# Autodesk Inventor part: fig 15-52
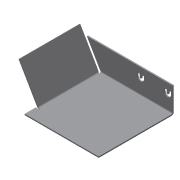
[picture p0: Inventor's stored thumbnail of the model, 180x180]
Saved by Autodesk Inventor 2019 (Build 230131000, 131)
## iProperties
Shininess: 77.0
Angle Display Precision: 2
Document Length Units: 11269
Document Angle Units: 11279
Document Time Units: 11290
Document Mass Units: 11283
Document Length Units Precision: 3
Document Angle Units Precision: 2
Created: 2002-04
Part Number: fig 15-52
Document SubType Name: Sheet Metal
Density: 1 g/cm^3
Sheet Metal Rule: Default
Material: Generic
Appearance: Default
Density: 0.0
Volumn: 0.0
Area: 0.0
PropertySet Name: Model Information
Control State: 0
Master: False
Checked Out: False
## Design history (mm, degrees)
node "Face1"
  sketch "Sketch1"
    geometry: L1 (12.647, 25.882)-(12.647, -14.118); L2 (12.647, -14.118)-(-17.353, -14.118); L3 (-17.353, -14.118)-(-17.353, 15.882); L4 (-17.353, 15.882)-(-2.353, 15.882); L5 (-2.353, 15.882)-(-2.353, 25.882); L6 (-2.353, 25.882)-(12.647, 25.882); 1 further point
    constraints: 12 end point, 4 parallel, 1 perpendicular
    dimensions: "d5" = 30 distance of L2.end L3.end; "d6" = 10 distance of L4.end L5.end; "d7" = 15 distance of L3.end L4.end; "d25" = 15 distance of L5.end L1.start
sketch "Sketch3"
  geometry: L1 (10, -15)-(10, 0)
  constraints: 2 end point
feature "Fold3" sketch "Sketch3" dims "d26" = 0.5 (= BendRadius), "d27" = 90 deg, "d28" = 0.5 (= BendRadius), "d96" = 0.5 (= BendReliefWidth), "d97" = 0.25 (= BendReliefDepth), "d98" = 1 (= MinimumRemnant), "d112" = 0.5 (= Thickness), "SeamGap" = 0.01
node "Flange2"
sketch "Sketch6"
  geometry: L1 (-6.914, 3.413)-(-5.843, 3.413); L2 (-5.843, 0.624)-(-6.914, 0.624); L3 (-6.914, 2.432)-(-5.843, 2.432); L4 (-5.843, 1.605)-(-6.914, 1.605); L5 (-6.914, 0.624)-(-6.914, 1.605); L6 (-6.914, 2.432)-(-6.914, 3.413); L7 (-6.914, 12.568)-(-6.914, 11.587); L8 (-6.914, 14.376)-(-6.914, 13.395); L9 (-6.914, 11.587)-(-5.843, 11.587); L10 (-5.843, 14.376)-(-6.914, 14.376); L11 (-6.914, 12.568)-(-5.843, 12.568); L12 (-5.843, 13.395)-(-6.914, 13.395); A1 r 1.394 centre (-5.843, 2.018) between (-5.843, 0.624) and (-5.843, 3.413); A2 r 0.413 centre (-5.843, 2.018) between (-5.843, 1.605) and (-5.843, 2.432); A3 r 1.394 centre (-5.843, 12.982) between (-5.843, 11.587) and (-5.843, 14.376); A4 r 0.413 centre (-5.843, 12.982) between (-5.843, 12.568) and (-5.843, 13.395)
  constraints: 24 end point, 8 point on circle, 4 centre point, 3 equal length, 1 perpendicular
cut "Cut1" sketch "Sketch6" dims "d49" = 0.5 (= Thickness), "d50" = 0
feature "Corner3" dims "d107" = 2 (= CornerReliefSize), "d108" = 0.5 (= BendRadius), "d109" = 0.5 (= GapSize), "d110" = 0, "d111" = 10, "d112" = 0.5 (= Thickness)
body "Solid1"
face "Plate1" dims "d112" = 0.5 (= Thickness)
sketch "Sketch5"
  geometry: L1 (20, 0)-(5, 0); L2 (5, 0)-(5, 15); L3 (5, 15)-(20, 15); L4 (20, 15)-(20, 0)
  constraints: 8 end point
face "Plate6" dims "d35" = 10, "d36" = 5, "d38" = 15, "d39" = 60 deg, "d40" = 0.5 (= BendRadius), "d112" = 0.5 (= Thickness), "MinimumRemnant" = 1 (= 2 x Thickness), "BendReliefWidth" = 0.5 (= Thickness)
bend "Bend5" dims "d38" = 15, "d39" = 60 deg, "d40" = 0.5 (= BendRadius), "d99" = 0.5 (= BendReliefWidth), "d100" = 0.25 (= BendReliefDepth), "d101" = 1 (= MinimumRemnant), "d112" = 0.5 (= Thickness), "SeamGap" = 0.01, "MinimumRemnant" = 1 (= 2 x Thickness), "BendReliefWidth" = 0.5 (= Thickness), "TransitionRadius" = 0.5 (= BendRadius)
other parameters: "Thickness" = 0.5, "BendRadius" = 0.5 (= Thickness), "BendReliefDepth" = 0.25 (= 0.5 x Thickness), "CornerReliefSize" = 2 (= 4 x Thickness), "d0" = 0.5 (= BendRadius), "d13" = 0.5 (= BendRadius), "d31" = 0.5 (= BendRadius), "d37" = 0.5 (= BendRadius), "JacobiRadiusSize" = 0.5 (= Thickness), "GapSize" = 0.5 (= Thickness)
